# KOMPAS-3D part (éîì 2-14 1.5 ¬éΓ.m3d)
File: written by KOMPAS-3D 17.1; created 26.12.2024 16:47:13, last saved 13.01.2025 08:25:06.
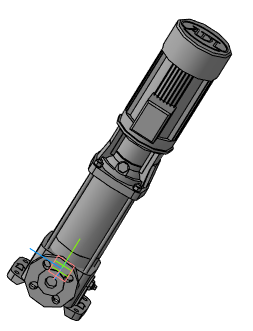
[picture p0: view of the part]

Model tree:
1. Операция без истории:4  (labels: ВМН 2-14 1.5 кВт)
